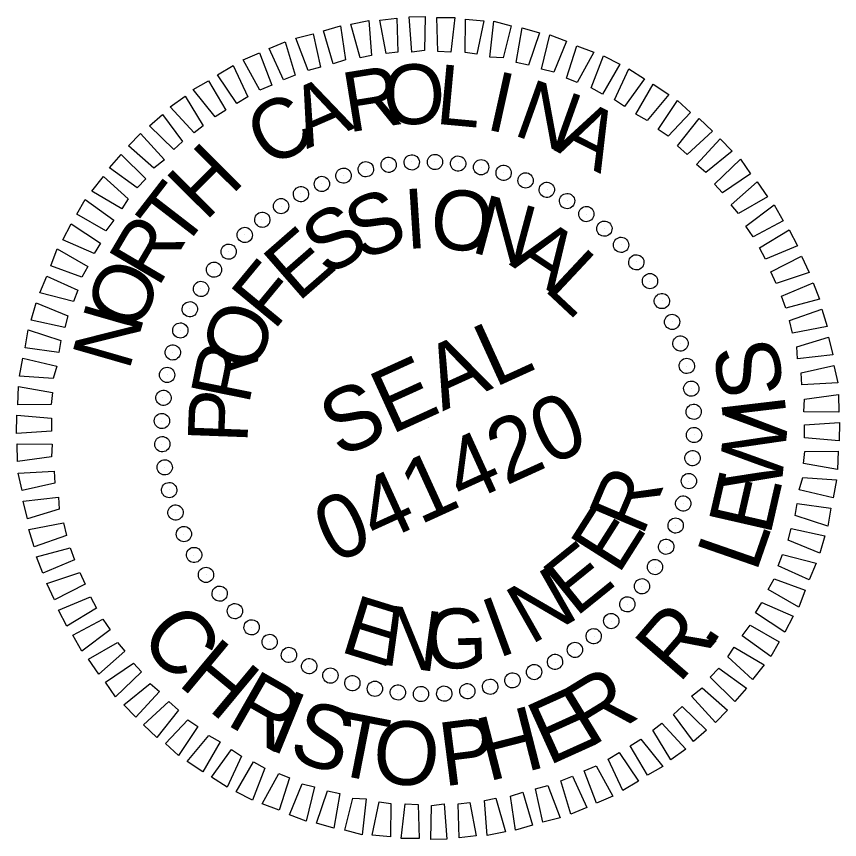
# Model space of a CAD drawing. Extents: x 2249019 to 2251039, y 663030 to 664799.
# Drawn here: x 2250900.4 to 2250977.9, y 664721.4 to 664799 of the extents above; entities that cross this region are included whole.
import ezdxf

# ---------------------------------------------------------------- set-up
doc = ezdxf.new("R2010")
doc.units = 0
doc.layers.add('Sheet PE Seal Cell', color=7, linetype='Continuous')

msp = doc.modelspace()

# ---------------------------------------------------------------- linework, layer by layer
at = {"layer": 'Sheet PE Seal Cell'}
for p, q in [((2250935.398, 664785.014), (2250935.398, 664785.014)), ((2250937.599, 664785.248), (2250937.599, 664785.248)), ((2250939.792, 664785.258), (2250939.792, 664785.258)), ((2250941.981, 664785.157), (2250941.981, 664785.157)), ((2250944.137, 664784.765), (2250944.137, 664784.765)), ((2250931.199, 664783.979), (2250931.199, 664783.979)), ((2250933.3, 664784.553), (2250933.3, 664784.553)), ((2250946.29, 664784.263), (2250946.29, 664784.263)), ((2250929.134, 664783.204), (2250929.134, 664783.204)), ((2250948.322, 664783.54), (2250948.322, 664783.54)), ((2250950.371, 664782.661), (2250950.371, 664782.661)), ((2250927.153, 664782.246), (2250927.153, 664782.246)), ((2250925.321, 664781.081), (2250925.321, 664781.081)), ((2250952.234, 664781.587), (2250952.234, 664781.587)), ((2250954.069, 664780.335), (2250954.069, 664780.335)), ((2250923.485, 664779.805), (2250923.485, 664779.805)), ((2250955.787, 664778.975), (2250955.787, 664778.975)), ((2250921.823, 664778.388), (2250921.823, 664778.388)), ((2250957.345, 664777.487), (2250957.345, 664777.487)), ((2250920.335, 664776.831), (2250920.335, 664776.831)), ((2250958.761, 664775.825), (2250958.761, 664775.825)), ((2250918.975, 664775.113), (2250918.975, 664775.113)), ((2250960.038, 664773.988), (2250960.038, 664773.988)), ((2250917.723, 664773.278), (2250917.723, 664773.278)), ((2250961.202, 664772.156), (2250961.202, 664772.156)), ((2250916.649, 664771.415), (2250916.649, 664771.415)), ((2250962.16, 664770.175), (2250962.16, 664770.175)), ((2250915.769, 664769.366), (2250915.769, 664769.366)), ((2250962.936, 664768.111), (2250962.936, 664768.111)), ((2250915.047, 664767.334), (2250915.047, 664767.334)), ((2250963.509, 664766.009), (2250963.509, 664766.009)), ((2250914.544, 664765.181), (2250914.544, 664765.181)), ((2250963.97, 664763.912), (2250963.97, 664763.912)), ((2250914.153, 664763.025), (2250914.153, 664763.025)), ((2250964.204, 664761.711), (2250964.204, 664761.711)), ((2250914.052, 664760.836), (2250914.052, 664760.836)), ((2250939.133, 664760.177), (2250939.133, 664760.177)), ((2250964.214, 664759.518), (2250964.214, 664759.518)), ((2250914.062, 664758.643), (2250914.062, 664758.643)), ((2250964.113, 664757.328), (2250964.113, 664757.328)), ((2250914.296, 664756.442), (2250914.296, 664756.442)), ((2250963.722, 664755.172), (2250963.722, 664755.172)), ((2250914.757, 664754.344), (2250914.757, 664754.344)), ((2250963.219, 664753.02), (2250963.219, 664753.02)), ((2250915.33, 664752.242), (2250915.33, 664752.242)), ((2250962.497, 664750.987), (2250962.497, 664750.987)), ((2250916.106, 664750.178), (2250916.106, 664750.178)), ((2250961.617, 664748.938), (2250961.617, 664748.938)), ((2250917.064, 664748.197), (2250917.064, 664748.197)), ((2250960.543, 664747.075), (2250960.543, 664747.075)), ((2250918.228, 664746.365), (2250918.228, 664746.365)), ((2250959.291, 664745.241), (2250959.291, 664745.241)), ((2250919.504, 664744.529), (2250919.504, 664744.529)), ((2250920.921, 664742.867), (2250920.921, 664742.867)), ((2250957.931, 664743.522), (2250957.931, 664743.522)), ((2250922.478, 664741.379), (2250922.478, 664741.379)), ((2250956.443, 664741.965), (2250956.443, 664741.965)), ((2250954.781, 664740.548), (2250954.781, 664740.548)), ((2250924.197, 664740.019), (2250924.197, 664740.019)), ((2250952.945, 664739.272), (2250952.945, 664739.272)), ((2250926.031, 664738.767), (2250926.031, 664738.767)), ((2250927.894, 664737.692), (2250927.894, 664737.692)), ((2250951.113, 664738.107), (2250951.113, 664738.107)), ((2250929.944, 664736.813), (2250929.944, 664736.813)), ((2250949.131, 664737.15), (2250949.131, 664737.15)), ((2250931.976, 664736.091), (2250931.976, 664736.091)), ((2250947.067, 664736.374), (2250947.067, 664736.374)), ((2250934.128, 664735.588), (2250934.128, 664735.588)), ((2250936.285, 664735.197), (2250936.285, 664735.197)), ((2250938.474, 664735.095), (2250938.474, 664735.095)), ((2250940.667, 664735.106), (2250940.667, 664735.106)), ((2250942.868, 664735.34), (2250942.868, 664735.34)), ((2250944.966, 664735.801), (2250944.966, 664735.801))]:
    msp.add_line(p, q, dxfattribs=at)
for points in [[(2250935.193, 664795.47), (2250934.59, 664798.602), (2250936.208, 664798.79), (2250936.294, 664795.587)], [(2250937.614, 664795.584), (2250937.354, 664798.928), (2250938.877, 664798.962), (2250938.806, 664795.743)], [(2250940.055, 664795.653), (2250939.97, 664798.856), (2250941.67, 664798.861), (2250941.284, 664795.609)], [(2250942.625, 664795.56), (2250942.672, 664798.713), (2250944.389, 664798.562), (2250943.738, 664795.408)], [(2250930.191, 664794.51), (2250929.274, 664797.608), (2250930.879, 664798.065), (2250931.346, 664794.871)], [(2250932.74, 664795.067), (2250931.847, 664798.231), (2250933.56, 664798.572), (2250933.799, 664795.275)], [(2250944.959, 664795.14), (2250945.349, 664798.505), (2250946.968, 664798.088), (2250946.209, 664795.05)], [(2250947.447, 664794.625), (2250947.99, 664797.895), (2250949.629, 664797.433), (2250948.602, 664794.382)], [(2250927.842, 664793.879), (2250926.676, 664796.919), (2250928.302, 664797.33), (2250929.016, 664794.194)], [(2250949.818, 664794.003), (2250950.606, 664797.219), (2250952.195, 664796.624), (2250950.994, 664793.714)], [(2250925.504, 664792.978), (2250924.157, 664795.936), (2250925.679, 664796.575), (2250926.617, 664793.431)], [(2250952.182, 664793.157), (2250953.164, 664796.187), (2250954.754, 664795.592), (2250953.196, 664792.74)], [(2250923.3, 664792.029), (2250921.725, 664794.883), (2250923.247, 664795.521), (2250924.412, 664792.481)], [(2250954.521, 664792.244), (2250955.681, 664795.246), (2250957.196, 664794.453), (2250955.573, 664791.625)], [(2250921.128, 664790.765), (2250919.301, 664793.449), (2250920.765, 664794.335), (2250922.158, 664791.399)], [(2250956.695, 664791.092), (2250958.053, 664794.019), (2250959.519, 664793.093), (2250957.634, 664790.476)], [(2250919.069, 664789.496), (2250917.014, 664792.077), (2250918.453, 664792.897), (2250920.099, 664790.131)], [(2250958.728, 664789.766), (2250960.351, 664792.593), (2250961.838, 664791.622), (2250959.779, 664789.146)], [(2250917.113, 664788.001), (2250914.851, 664790.432), (2250916.253, 664791.455), (2250917.965, 664788.664)], [(2250960.823, 664788.303), (2250962.645, 664791.056), (2250963.879, 664789.915), (2250961.763, 664787.687)], [(2250915.199, 664786.414), (2250912.908, 664788.667), (2250914.132, 664789.719), (2250916.009, 664787.168)], [(2250962.624, 664786.761), (2250964.687, 664789.349), (2250965.942, 664788.163), (2250963.535, 664785.967)], [(2250913.301, 664784.67), (2250910.915, 664786.77), (2250912.032, 664787.938), (2250914.314, 664785.462)], [(2250964.418, 664784.996), (2250966.654, 664787.443), (2250967.797, 664786.261), (2250965.308, 664784.247)], [(2250911.734, 664782.802), (2250909.117, 664784.687), (2250910.238, 664785.967), (2250912.549, 664783.668)], [(2250966.141, 664783.143), (2250968.576, 664785.517), (2250969.533, 664784.14), (2250966.895, 664782.333)], [(2250910.275, 664780.819), (2250907.472, 664782.509), (2250908.551, 664783.88), (2250910.891, 664781.759)], [(2250967.682, 664781.208), (2250970.155, 664783.379), (2250971.132, 664781.956), (2250968.39, 664780.377)], [(2250908.792, 664778.769), (2250906.051, 664780.323), (2250906.84, 664781.726), (2250909.544, 664779.771)], [(2250969.087, 664779.211), (2250971.754, 664781.196), (2250972.595, 664779.711), (2250969.766, 664778.202)], [(2250907.685, 664776.616), (2250904.733, 664777.909), (2250905.526, 664779.424), (2250908.28, 664777.602)], [(2250970.355, 664777.151), (2250973.146, 664778.863), (2250973.942, 664777.358), (2250970.943, 664776.101)], [(2250906.508, 664774.377), (2250903.593, 664775.466), (2250904.188, 664777.056), (2250907.082, 664775.408)], [(2250971.437, 664774.897), (2250974.332, 664776.381), (2250975.037, 664774.834), (2250971.935, 664773.805)], [(2250905.732, 664772.1), (2250902.561, 664772.908), (2250903.222, 664774.473), (2250906.128, 664773.16)], [(2250972.428, 664772.602), (2250975.427, 664773.858), (2250976.02, 664772.315), (2250972.835, 664771.468)], [(2250904.927, 664769.645), (2250901.753, 664770.342), (2250902.215, 664771.981), (2250905.191, 664770.755)], [(2250973.196, 664770.314), (2250976.232, 664771.368), (2250976.755, 664769.738), (2250973.466, 664769.118)], [(2250904.35, 664767.294), (2250901.188, 664767.722), (2250901.452, 664769.435), (2250904.548, 664768.428)], [(2250973.889, 664767.828), (2250976.876, 664768.749), (2250977.262, 664767.057), (2250973.961, 664766.706)], [(2250903.815, 664764.853), (2250900.645, 664765.056), (2250900.974, 664766.745), (2250904.169, 664766.003)], [(2250974.293, 664765.374), (2250977.383, 664766.068), (2250977.749, 664764.421), (2250974.364, 664764.253)], [(2250903.614, 664762.398), (2250900.502, 664762.354), (2250900.542, 664764.076), (2250903.766, 664763.512)], [(2250974.606, 664762.879), (2250977.8, 664763.346), (2250977.851, 664761.666), (2250974.541, 664761.696)], [(2250903.658, 664759.891), (2250900.36, 664759.652), (2250900.4, 664761.373), (2250903.657, 664761.099)], [(2250974.608, 664760.463), (2250977.906, 664760.702), (2250977.866, 664758.98), (2250974.609, 664759.254)], [(2250903.66, 664757.474), (2250900.466, 664757.008), (2250900.415, 664758.688), (2250903.725, 664758.658)], [(2250974.652, 664757.955), (2250977.763, 664757.999), (2250977.724, 664756.278), (2250974.5, 664756.842)], [(2250903.973, 664754.979), (2250900.882, 664754.285), (2250900.517, 664755.932), (2250903.901, 664756.101)], [(2250974.451, 664755.501), (2250977.621, 664755.297), (2250977.292, 664753.608), (2250974.096, 664754.35)], [(2250904.376, 664752.526), (2250901.39, 664751.604), (2250901.003, 664753.296), (2250904.305, 664753.647)], [(2250973.916, 664753.059), (2250977.077, 664752.632), (2250976.814, 664750.918), (2250973.718, 664751.925)], [(2250905.07, 664750.04), (2250902.034, 664748.986), (2250901.511, 664750.616), (2250904.8, 664751.235)], [(2250973.338, 664750.708), (2250976.513, 664750.012), (2250976.051, 664748.373), (2250973.075, 664749.599)], [(2250905.838, 664747.752), (2250902.839, 664746.495), (2250902.245, 664748.038), (2250905.431, 664748.885)], [(2250972.534, 664748.253), (2250975.704, 664747.445), (2250975.044, 664745.881), (2250972.138, 664747.194)], [(2250906.829, 664745.456), (2250903.933, 664743.972), (2250903.229, 664745.519), (2250906.331, 664746.548)], [(2250971.758, 664745.977), (2250974.672, 664744.887), (2250974.078, 664743.298), (2250971.184, 664744.946)], [(2250907.911, 664743.202), (2250905.119, 664741.49), (2250904.323, 664742.996), (2250907.322, 664744.253)], [(2250970.581, 664743.737), (2250973.532, 664742.445), (2250972.739, 664740.929), (2250969.986, 664742.752)], [(2250909.179, 664741.143), (2250906.512, 664739.158), (2250905.67, 664740.643), (2250908.499, 664742.152)], [(2250969.474, 664741.584), (2250972.215, 664740.031), (2250971.426, 664738.627), (2250968.722, 664740.582)], [(2250910.584, 664739.145), (2250908.111, 664736.975), (2250907.133, 664738.397), (2250909.875, 664739.976)], [(2250967.99, 664739.534), (2250970.793, 664737.845), (2250969.715, 664736.474), (2250967.375, 664738.595)], [(2250912.125, 664737.21), (2250909.69, 664734.837), (2250908.733, 664736.214), (2250911.371, 664738.02)], [(2250966.531, 664737.551), (2250969.148, 664735.666), (2250968.028, 664734.387), (2250965.717, 664736.685)], [(2250913.848, 664735.358), (2250911.612, 664732.91), (2250910.468, 664734.093), (2250912.958, 664736.106)], [(2250964.965, 664735.683), (2250967.35, 664733.583), (2250966.234, 664732.415), (2250963.952, 664734.892)], [(2250915.641, 664733.593), (2250913.579, 664731.004), (2250912.324, 664732.191), (2250914.73, 664734.386)], [(2250963.067, 664733.939), (2250965.358, 664731.686), (2250964.134, 664730.634), (2250962.257, 664733.185)], [(2250917.443, 664732.051), (2250915.621, 664729.297), (2250914.387, 664730.438), (2250916.503, 664732.666)], [(2250961.153, 664732.353), (2250963.414, 664729.922), (2250962.013, 664728.898), (2250960.301, 664731.69)], [(2250919.538, 664730.588), (2250917.915, 664727.76), (2250916.428, 664728.731), (2250918.487, 664731.208)], [(2250959.197, 664730.857), (2250961.252, 664728.277), (2250959.812, 664727.456), (2250958.167, 664730.223)], [(2250921.571, 664729.261), (2250920.213, 664726.335), (2250918.747, 664727.26), (2250920.631, 664729.877)], [(2250957.137, 664729.589), (2250958.965, 664726.905), (2250957.501, 664726.018), (2250956.108, 664728.955)], [(2250923.745, 664728.109), (2250922.585, 664725.108), (2250921.07, 664725.901), (2250922.693, 664728.729)], [(2250954.966, 664728.325), (2250956.541, 664725.471), (2250955.019, 664724.832), (2250953.853, 664727.873)], [(2250926.084, 664727.197), (2250925.102, 664724.167), (2250923.512, 664724.761), (2250925.069, 664727.614)], [(2250952.761, 664727.375), (2250954.109, 664724.418), (2250952.587, 664723.779), (2250951.649, 664726.923)], [(2250928.447, 664726.351), (2250927.66, 664723.135), (2250926.07, 664723.729), (2250927.272, 664726.639)], [(2250930.819, 664725.728), (2250930.276, 664722.459), (2250928.637, 664722.92), (2250929.664, 664725.971)], [(2250948.074, 664725.844), (2250948.992, 664722.745), (2250947.387, 664722.288), (2250946.92, 664725.483)], [(2250950.424, 664726.475), (2250951.59, 664723.434), (2250949.964, 664723.023), (2250949.249, 664726.159)], [(2250933.306, 664725.213), (2250932.916, 664721.849), (2250931.298, 664722.265), (2250932.057, 664725.303)], [(2250945.526, 664725.287), (2250946.419, 664722.122), (2250944.706, 664721.781), (2250944.467, 664725.079)], [(2250935.641, 664724.793), (2250935.594, 664721.64), (2250933.876, 664721.792), (2250934.527, 664724.945)], [(2250938.21, 664724.701), (2250938.296, 664721.498), (2250936.595, 664721.492), (2250936.981, 664724.745)], [(2250940.652, 664724.769), (2250940.911, 664721.426), (2250939.389, 664721.391), (2250939.46, 664724.611)], [(2250943.072, 664724.883), (2250943.675, 664721.751), (2250942.058, 664721.563), (2250941.972, 664724.766)]]:
    msp.add_lwpolyline(points, close=True, dxfattribs=at)
for centre, major_axis in [((2250935.427, 664784.981), (-0.106, 0.712)), ((2250937.603, 664785.21), (-0.044, 0.719)), ((2250939.79, 664785.248), (0.019, 0.72)), ((2250941.973, 664785.095), (0.082, 0.715)), ((2250944.134, 664784.753), (0.144, 0.706)), ((2250931.176, 664783.961), (-0.228, 0.683)), ((2250933.279, 664784.564), (-0.168, 0.7)), ((2250946.257, 664784.224), (0.205, 0.69)), ((2250929.133, 664783.177), (-0.287, 0.66)), ((2250948.326, 664783.511), (0.264, 0.67)), ((2250950.324, 664782.621), (0.321, 0.644)), ((2250927.167, 664782.218), (-0.344, 0.633)), ((2250952.238, 664781.56), (0.376, 0.614)), ((2250925.291, 664781.091), (-0.397, 0.6)), ((2250954.052, 664780.337), (0.428, 0.579)), ((2250923.521, 664779.805), (-0.448, 0.563)), ((2250955.752, 664778.96), (0.477, 0.539)), ((2250921.87, 664778.37), (-0.496, 0.522)), ((2250957.326, 664777.44), (0.522, 0.496)), ((2250920.35, 664776.796), (-0.539, 0.477)), ((2250958.761, 664775.789), (0.563, 0.448)), ((2250918.973, 664775.096), (-0.579, 0.428)), ((2250960.047, 664774.019), (0.6, 0.397)), ((2250917.749, 664773.282), (-0.614, 0.376)), ((2250961.174, 664772.143), (0.633, 0.344)), ((2250916.688, 664771.368), (-0.644, 0.321)), ((2250962.133, 664770.177), (0.66, 0.287)), ((2250915.798, 664769.369), (-0.67, 0.264)), ((2250962.917, 664768.134), (0.683, 0.228)), ((2250915.086, 664767.301), (-0.69, 0.205)), ((2250963.52, 664766.031), (0.7, 0.168)), ((2250914.557, 664765.178), (-0.706, 0.144)), ((2250963.938, 664763.883), (0.712, 0.106)), ((2250914.214, 664763.017), (-0.715, 0.082)), ((2250964.166, 664761.707), (0.719, 0.044)), ((2250914.061, 664760.834), (-0.72, 0.019)), ((2250964.204, 664759.519), (0.72, -0.019)), ((2250914.1, 664758.647), (-0.719, -0.044)), ((2250964.052, 664757.337), (0.715, -0.082)), ((2250914.328, 664756.471), (-0.712, -0.106)), ((2250963.709, 664755.176), (0.706, -0.144)), ((2250914.746, 664754.323), (-0.7, -0.168)), ((2250963.18, 664753.053), (0.69, -0.205)), ((2250915.349, 664752.22), (-0.683, -0.228)), ((2250962.467, 664750.984), (0.67, -0.264)), ((2250916.133, 664750.177), (-0.66, -0.287)), ((2250961.577, 664748.985), (0.644, -0.321)), ((2250917.092, 664748.21), (-0.633, -0.344)), ((2250960.517, 664747.072), (0.614, -0.376)), ((2250918.219, 664746.335), (-0.6, -0.397)), ((2250959.293, 664745.258), (0.579, -0.428)), ((2250919.504, 664744.565), (-0.563, -0.448)), ((2250957.916, 664743.558), (0.539, -0.477)), ((2250920.94, 664742.913), (-0.522, -0.496)), ((2250922.514, 664741.394), (-0.477, -0.539)), ((2250956.396, 664741.984), (0.496, -0.522)), ((2250954.745, 664740.548), (0.448, -0.563)), ((2250924.214, 664740.017), (-0.428, -0.579)), ((2250952.975, 664739.262), (0.397, -0.6)), ((2250926.028, 664738.793), (-0.376, -0.614)), ((2250951.099, 664738.136), (0.344, -0.633)), ((2250927.941, 664737.732), (-0.321, -0.644)), ((2250929.94, 664736.842), (-0.264, -0.67)), ((2250949.133, 664737.177), (0.287, -0.66)), ((2250932.009, 664736.13), (-0.205, -0.69)), ((2250947.09, 664736.392), (0.228, -0.683)), ((2250934.132, 664735.6), (-0.144, -0.706)), ((2250936.293, 664735.258), (-0.082, -0.715)), ((2250938.475, 664735.105), (-0.019, -0.72)), ((2250940.663, 664735.143), (0.044, -0.719)), ((2250942.839, 664735.372), (0.106, -0.712)), ((2250944.987, 664735.789), (0.168, -0.7))]:
    msp.add_ellipse(centre, major_axis=major_axis, ratio=0.999708, dxfattribs=at)

# ---------------------------------------------------------------- texts
for s, height, rotation, p in [('R', 5.638, 9.11904, (2250931.613, 664788.014)), ('O', 5.638, 1.91911, (2250934.972, 664788.721)), ('L', 5.638, 354.71882, (2250939.743, 664788.862)), ('I', 5.638, 347.51808, (2250944.424, 664788.358)), ('A', 5.638, 23.51826, (2250927.708, 664786.455)), ('N', 5.639, 340.31685, (2250947.023, 664787.839)), ('C', 5.638, 30.71781, (2250924.238, 664784.544)), ('A', 5.639, 333.1151, (2250950.931, 664786.377)), ('H', 5.638, 45.11742, (2250918.151, 664779.573)), ('T', 5.638, 52.31772, (2250915.878, 664776.723)), ('S', 5.638, 22.39834, (2250932.853, 664775.887)), ('I', 5.638, 3.68755, (2250937.056, 664777.033)), ('O', 5.638, 354.33143, (2250939.166, 664777.225)), ('N', 5.638, 344.97455, (2250943.044, 664776.795)), ('S', 5.638, 31.75355, (2250929.598, 664774.349)), ('R', 5.638, 59.51845, (2250913.696, 664773.312)), ('E', 5.638, 41.10901, (2250926.894, 664771.963)), ('A', 5.639, 326.25821, (2250946.716, 664775.61)), ('L', 5.639, 316.89879, (2250949.921, 664773.28)), ('F', 5.638, 50.46498, (2250924.604, 664769.271)), ('O', 5.638, 66.71968, (2250911.842, 664769.06)), ('N', 5.639, 73.92144, (2250910.952, 664765.468)), ('O', 5.639, 69.17918, (2250922.824, 664765.218)), ('SEAL', 5.9982, 24.49794, (2250930.774, 664757.3)), ('R', 5.639, 78.53759, (2250922.248, 664762.263)), ('S', 5.998, 100.55241, (2250972.78, 664763.578)), ('P', 5.639, 87.89683, (2250922.119, 664758.688)), ('041420', 5.9982, 24.49794, (2250930.224, 664747.317)), ('I', 5.998, 96.75046, (2250972.931, 664761.34)), ('W', 5.998, 84.21639, (2250972.378, 664753.977)), ('R', 5.639, 66.97935, (2250959.324, 664749.871)), ('E', 5.998, 77.10705, (2250971.355, 664749.91)), ('E', 5.638, 57.62203, (2250957.068, 664746.261)), ('L', 5.998, 70.83229, (2250970.04, 664746.45)), ('E', 5.638, 38.9097, (2250953.054, 664742.289)), ('N', 5.638, 29.55433, (2250948.798, 664739.69)), ('E', 5.638, 342.77483, (2250930.699, 664739.135)), ('I', 5.638, 20.19914, (2250945.687, 664738.438)), ('C', 5.998, 310.69992, (2250911.746, 664740.337)), ('N', 5.638, 352.1319, (2250934.548, 664737.922)), ('G', 5.638, 1.48818, (2250938.939, 664737.45)), ('R', 5.998, 49.11789, (2250962.768, 664735.989)), ('.', 5.998, 56.59815, (2250965.716, 664739.272)), ('H', 5.998, 320.28207, (2250915.43, 664736.055)), ('R', 5.998, 330.26605, (2250919.971, 664732.311)), ('R', 5.998, 31.43728, (2250954.306, 664729.953)), ('I', 5.998, 337.74631, (2250923.762, 664730.054)), ('E', 5.998, 24.32794, (2250950.448, 664728.308)), ('S', 5.998, 341.54826, (2250925.793, 664729.101)), ('T', 5.998, 348.87397, (2250929.865, 664727.653)), ('H', 5.998, 14.34395, (2250944.752, 664726.829)), ('P', 5.998, 7.23461, (2250940.581, 664726.39)), ('O', 5.998, 355.67421, (2250933.781, 664726.785))]:
    msp.add_text(s, height=height, rotation=rotation, dxfattribs=at).set_placement(p)

doc.saveas('drawing.dxf')
